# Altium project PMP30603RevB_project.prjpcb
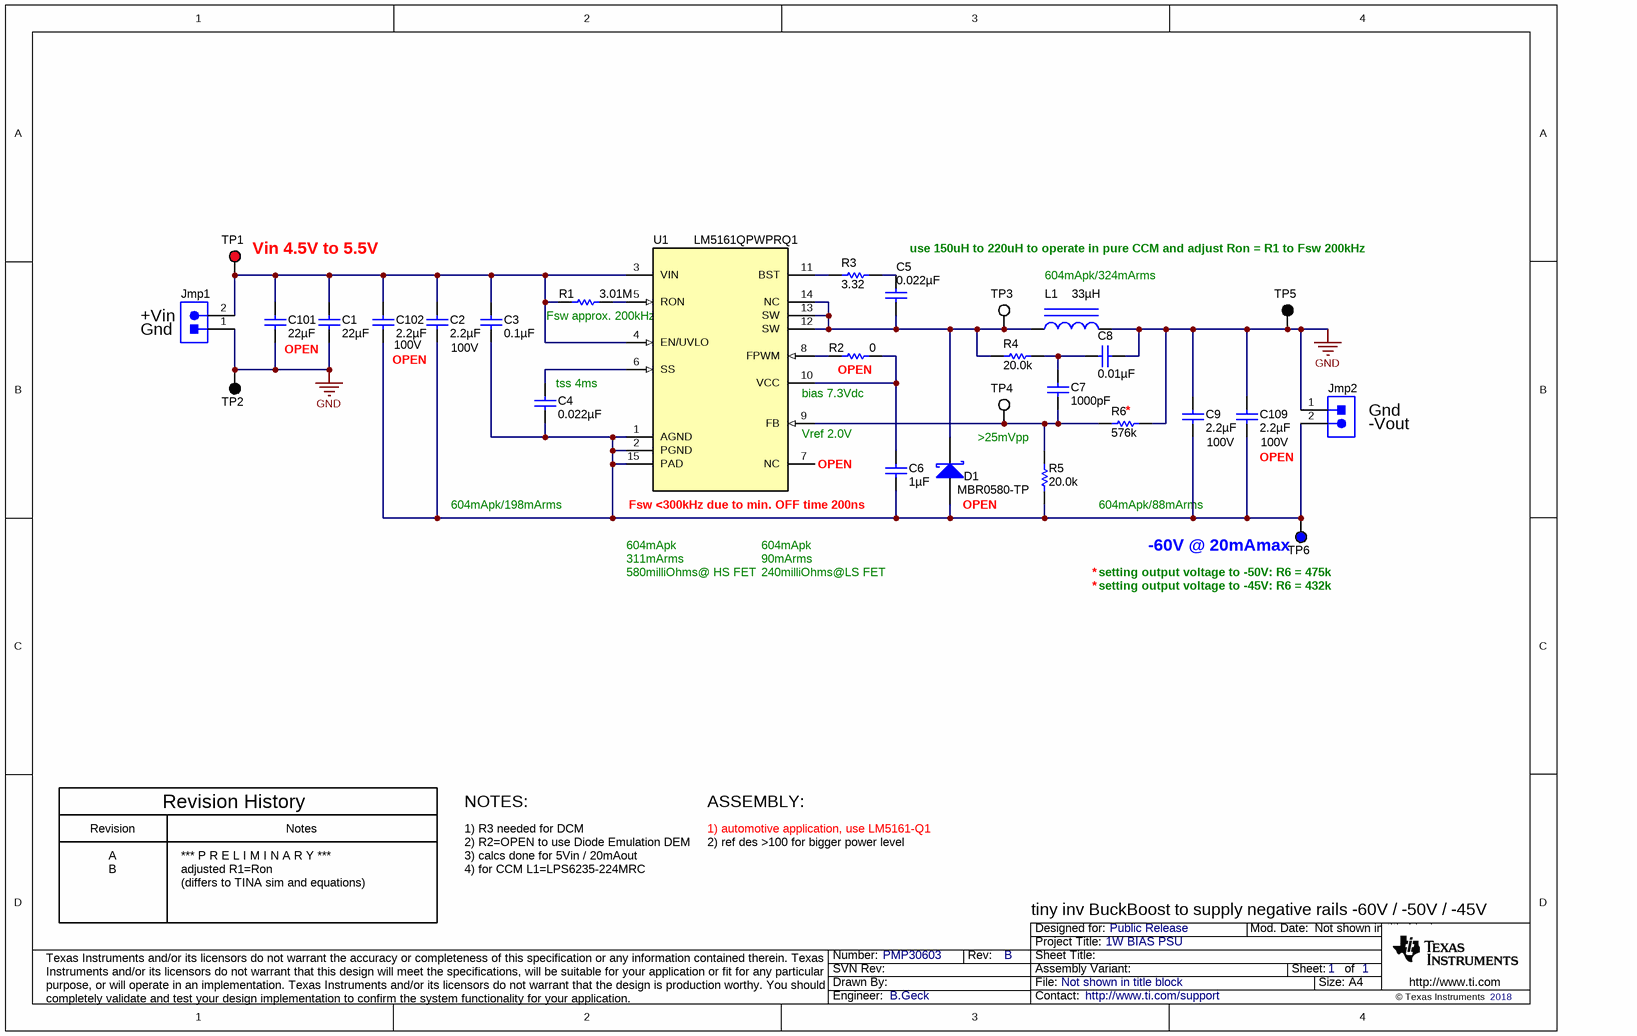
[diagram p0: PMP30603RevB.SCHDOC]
CopyrightYear: 2018; PCB_Layout: B.Geck; PCB_Rev: A; PRJ_Customer: Public Release; PRJ_Engineer: B.Geck; PRJ_Number: PMP30603; PRJ_Title: 1W BIAS PSU; SCH_Rev: B; TechSupport: http://www.ti.com/support
1 sheet, 29 parts. Net scope: global (net labels, ports and power ports of the same name join across sheets).
Board file: PMP30603RevA_board.PcbDoc

## Sheet PMP30603RevB.SCHDOC
size A4; Date: Not shown in title block; ApprovedBy: Not shown in title block; CheckedBy: Not shown in title block; Author: Not shown in title block; CompanyName: Not shown in title block; Engineer: Not shown in title block; Organization: Not shown in title block; Address1: Not shown in title block; Address2: Not shown in title block; Address3: Not shown in title block; Address4: Not shown in title block; DocumentNumber: 1; Revision: Use project parameter SCH_Rev; SheetNumber: 1; SheetTotal: 1; PageSetup: Record=PageOptions¦CenterHorizontal=True¦CenterVertical=True¦PrintScale=0.70¦XCorrection=1.00¦YCorrection=1.00¦PrintKind=0¦BorderSize=5000000¦LeftOffset=0¦BottomOffset=0¦Orientation=2¦PaperLength=1000¦PaperWidth=1000¦Scale=100¦PaperSource=15¦PrintQuality=600¦MediaType=1¦DitherType=10¦PaperKind=A4¦PrintScaleMode=1

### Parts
C1  ValueDisplayed: 22µF  [1206_180]  (hidden comment: GCM31CR71A226KE02)
C2  ValueDisplayed: 2.2µF  Value2: 100V  [1206_190]  (hidden comment: GRM31CR72A225KA73L)
C3  ValueDisplayed: 0.1µF  [0603]  (hidden comment: GRM188R72A104KA35D)
C4  ValueDisplayed: 0.022µF  [0603]  (hidden comment: GRM188R71C223KA01D)
C5  ValueDisplayed: 0.022µF  [0603]  (hidden comment: GRM188R71C223KA01D)
C6  ValueDisplayed: 1µF  [0603]  (hidden comment: GRM188R71E105KA12D)
C7  ValueDisplayed: 1000pF  [0603]  (hidden comment: GRM188R72A102KA01D)
C8  ValueDisplayed: 0.01µF  [0603]  (hidden comment: GRM188R72A103KA01D)
C9  ValueDisplayed: 2.2µF  Value2: 100V  [1206_190]  (hidden comment: GRM31CR72A225KA73L)
C101  ValueDisplayed: 22µF  [1206_180]  (hidden comment: GCM31CR71A226KE02)
C102  ValueDisplayed: 2.2µF  Value2: 100V  [1206_190]  (hidden comment: GRM31CR72A225KA73L)
C109  ValueDisplayed: 2.2µF  Value2: 100V  [1206_190]  (hidden comment: GRM31CR72A225KA73L)
D1  MBR0580-TP  [SOD-123]
Jmp1  TSW-102-07-G-S  [TSW-102-07-G-S]  (value not drawn)
Jmp2  TSW-102-07-G-S  [TSW-102-07-G-S]  (value not drawn)
L1  ValueDisplayed: 33µH  [LPS6235]  (hidden comment: LPS6235-333MLB)
R1  ValueDisplayed: 3.01M  [0603]  (hidden comment: CRCW06033M01FKEA)
R2  ValueDisplayed: 0  [0603]  (hidden comment: CRCW06030000Z0EA)
R3  ValueDisplayed: 3.32  [0603]  (hidden comment: CRCW06033R32FKEA)
R4  ValueDisplayed: 20.0k  [0603]  (hidden comment: CRCW060320K0FKEA)
R5  ValueDisplayed: 20.0k  [0603]  (hidden comment: CRCW060320K0FKEA)
R6  ValueDisplayed: 576k  [0603]  (hidden comment: CRCW0603576KFKEA)
TP1  5000  [Keystone5000]  (value not drawn)
TP2  5001  [Keystone5001]  (value not drawn)
TP3  5002  [Keystone5002]  (value not drawn)
TP4  5002  [Keystone5002]  (value not drawn)
TP5  5001  [Keystone5001]  (value not drawn)
TP6  5117  [Keystone5117]  (value not drawn)
U1  LM5161QPWPRQ1  [PWP0014A_N]

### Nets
GND: C1.2 C8.1 C9.1 C101.2 C109.1 Jmp1.1 Jmp2.1 L1.2 R6.2 TP2.1 TP5.1
NetC1_1: C1.1 C2.1 C3.1 C101.1 C102.1 Jmp1.2 R1.1 TP1.1 U1.3(VIN) U1.4(EN/UVLO)
NetC2_2: C2.2 C3.2 C4.2 C6.2 C9.2 C102.2 C109.2 D1.2(A) Jmp2.2 R5.1 TP6.1 U1.1(AGND) U1.2(PGND) U1.15(PAD)
NetC4_1: C4.1 U1.6(SS)
NetC5_1: C5.1 R3.2
NetC5_2: C5.2 D1.1(K) L1.1 R4.1 TP3.1 U1.12(SW) U1.13(SW) U1.14(NC)
NetC6_1: C6.1 R2.2 U1.10(VCC)
NetC7_1: C7.1 C8.2 R4.2
NetC7_2: C7.2 R5.2 R6.1 TP4.1 U1.9(FB)
NetR1_2: R1.2 U1.5(RON)
NetR2_1: R2.1 U1.8(FPWM)
NetR3_1: R3.1 U1.11(BST)

Not connected (* = marked no-connect by the designer): U1 7(NC)

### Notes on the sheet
- (near TP1) Vin 4.5V to 5.5V
- use 150uH to 220uH to operate in pure CCM and adjust Ron = R1 to Fsw 200kHz
- (near Jmp1) +Vin
- (near U1) Fsw approx. 200kHz
- 604mApk/324mArms
- (near Jmp1) Gnd
- OPEN
- (near C4) tss 4ms
- (near R2) OPEN
- (near U1) Vref 2.0V
- (near U1) bias 7.3Vdc
- >25mVpp
- (near R6) *
- (near Jmp2) Gnd
- (near Jmp2) -Vout
- 604mApk/198mArms
- Fsw <300kHz due to min. OFF time 200ns
- (near D1) OPEN
- 604mApk/88mArms
- 604mApk
- 580milliOhms@ HS FET
- 311mArms
- 240milliOhms@LS FET
- 90mArms
- *
- (near TP6) setting output voltage to -50V: R6 = 475k
- (near TP6) setting output voltage to -45V: R6 = 432k
- (near TP6) -60V @ 20mAmax
- Revision
- A
- *** P R E L I M I N A R Y ***
- Revision History
- Notes
- NOTES:
- 3) calcs done for 5Vin / 20mAout
- 1) R3 needed for DCM
- 2) R2=OPEN to use Diode Emulation DEM
- ASSEMBLY:
- 1) automotive application, use LM5161-Q1
- 2) ref des >100 for bigger power level
- B
- adjusted R1=Ron
- (differs to TINA sim and equations)
- 4) for CCM L1=LPS6235-224MRC
- tiny inv BuckBoost to supply negative rails -60V / -50V / -45V

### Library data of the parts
C1 C101 = GCM31CR71A226KE02: CAP, CERM, 22 µF, 10 V,+/- 10%, X7R, AEC-Q200 Grade 1, 1206; Manufacturer: MuRata; Polarized: N; CompType: Capacitor; Value: 22uF; U/M: EA; Cap_F: 0.000022; Tolerance_%: 10; Value2: 10V; TaMin_C: -55; TaMax_C: 125; Cap_Case: 1206; SizeArea_mm2: 5.12; SizeAreaWB_mm2: 10.92; SizeX_mm: 3.2; SizeY_mm: 1.6; SizeZ_mm: 1.8; AEC Category: Q200; AEC Qualified: Y; AEC Grade: 1
C2 C9 C102 C109 = GRM31CR72A225KA73L: CAP, CERM, 2.2 µF, 100 V,+/- 10%, X7R, 1206; Manufacturer: MuRata; Polarized: N; CompType: Capacitor; Value: 2.2uF; U/M: EA; Cap_F: 0.0000022; Tolerance_%: 10; VDC_V: 100; TaMin_C: -55; TaMax_C: 125; Cap_Case: 1206; SizeArea_mm2: 5.12; SizeAreaWB_mm2: 10.92; SizeX_mm: 3.2; SizeY_mm: 1.6; SizeZ_mm: 1.9; AEC Category: Q200; Green_Lifecycle: Active; Green_REACh: Passed
C3 = GRM188R72A104KA35D: CAP, CERM, 0.1 µF, 100 V,+/- 10%, X7R, 0603; Manufacturer: MuRata; Polarized: N; CompType: Capacitor; Value: 0.1uF; U/M: EA; Cap_F: 0.0000001; Tolerance_%: 10; Value1: Unknown; VDC_V: 100; Value2: 100V; TaMin_C: -55; TaMax_C: 125; SizeArea_mm2: 1.28; SizeAreaWB_mm2: 4.68; SizeX_mm: 1.6; SizeY_mm: 0.8; SizeZ_mm: 1; AEC Category: Q200; Green_Lifecycle: Active; Green_REACh: Passed
C4 C5 = GRM188R71C223KA01D: CAP, CERM, 0.022 µF, 16 V,+/- 10%, X7R, 0603; Manufacturer: MuRata; Polarized: N; CompType: Capacitor; Value: 0.022uF; U/M: EA; Cap_F: 0.000000022; Tolerance_%: 10; VDC_V: 16; Value2: 16V; TaMin_C: -55; TaMax_C: 125; SizeArea_mm2: 1.28; SizeAreaWB_mm2: 4.68; SizeX_mm: 1.6; SizeY_mm: 0.8; SizeZ_mm: 1; AEC Category: Q200; Green_Lifecycle: Active; Green_REACh: Passed
C6 = GRM188R71E105KA12D: CAP, CERM, 1 µF, 25 V,+/- 10%, X7R, 0603; Manufacturer: MuRata; Polarized: N; CompType: Capacitor; Value: 1uF; U/M: EA; Cap_F: 0.000001; Tolerance_%: 10; VDC_V: 25; Value2: 25V; TaMin_C: -55; TaMax_C: 125; SizeArea_mm2: 1.28; SizeAreaWB_mm2: 4.68; SizeX_mm: 1.6; SizeY_mm: 0.8; SizeZ_mm: 1; AEC Category: Q200; Green_Lifecycle: Active; Green_REACh: Passed
C7 = GRM188R72A102KA01D: CAP, CERM, 1000 pF, 100 V,+/- 10%, X7R, 0603; Manufacturer: MuRata; Polarized: N; CompType: Capacitor; Value: 1000pF; U/M: EA; Cap_F: 0.000000001; Tolerance_%: 10; VDC_V: 100; Value2: 100V; TaMin_C: -55; TaMax_C: 125; SizeArea_mm2: 1.28; SizeAreaWB_mm2: 4.68; SizeX_mm: 1.6; SizeY_mm: 0.8; SizeZ_mm: 1; AEC Category: Q200; Green_Lifecycle: Active; Green_REACh: Passed
C8 = GRM188R72A103KA01D: CAP, CERM, 0.01 µF, 100 V,+/- 10%, X7R, 0603; Manufacturer: MuRata; Polarized: N; CompType: Capacitor; Value: 0.01uF; U/M: EA; Cap_F: 0.00000001; Tolerance_%: 10; VDC_V: 100; Value2: 100V; TaMin_C: -55; TaMax_C: 125; SizeArea_mm2: 1.28; SizeAreaWB_mm2: 4.68; SizeX_mm: 1.6; SizeY_mm: 0.8; SizeZ_mm: 1; AEC Category: Q200; Green_Lifecycle: Active; Green_REACh: Passed
D1 = MBR0580-TP: Diode, Schottky, 80 V, 0.5 A, SOD-123; Manufacturer: Micro Commercial Components; U/M: EA; Vf_V: 0.8; Value: 80V; Value1: 0.5A; Value2: 0.8V; Io_A: 0.5; Vr_V: 80; TJmax_C: 150; SizeAreaWB_mm2: 13.095; SizeArea_mm2: 6.545; SizeX_mm: 3.85; SizeY_mm: 1.7; SizeZ_mm: 1.35; AEC Category: Q101; Green_Lifecycle: Not Set; Green_REACh: Incomplete
Jmp1 Jmp2 = TSW-102-07-G-S: Header, 100mil, 2x1, Gold, TH; Manufacturer: Samtec; SymbolCreator: a0412235; U/M: EA
L1 = LPS6235-333MLB: Inductor, Shielded Drum Core, Ferrite, 33 µH, 1.3 A, 0.18 ohm, SMD; Manufacturer: Coilcraft; Value: 33uH; Ind_H: 33.0E-6; Imax_A: 1.3; Irms: 1.3A @ 40C rise; Isat: 1.5A @ 30% inductance drop; DCR_ohm: 0.18; Value2: 1.3A; SizeAreaWB_mm2: 64; SizeArea_mm2: 36; SizeX_mm: 6; SizeZ_mm: 3.5; AEC Category: Q200; Green_Lifecycle: Not Set; Green_REACh: Incomplete
R1 = CRCW06033M01FKEA: RES, 3.01 M, 1%, 0.1 W, 0603; Manufacturer: Vishay-Dale; CompType: Resistor; Value: 3.01Meg; Res_ohm: 3010000; Value_Code: 3M01; Tolerance_%: 1; Power_W: 0.1; Value2: 0.1W; VDC_V: 75; TempCo: 100 ppm/C; SizeArea_mm2: 1.28; SizeX_mm: 1.6; SizeY_mm: 0.8; EIA_Code: E96; U/M: EA; AEC Category: Q200; Green_Lifecycle: Active; Green_REACh: Passed
R2 = CRCW06030000Z0EA: RES, 0, 5%, 0.1 W, 0603; Manufacturer: Vishay-Dale; CompType: Resistor; Value: 0; Value_Code: 0000; Tolerance_%: 5; Power_W: 0.1; Value2: 0.1W; VDC_V: 75; TempCo: 200 ppm/C; SizeArea_mm2: 1.28; SizeX_mm: 1.6; SizeY_mm: 0.8; SizeZ_mm: 1; EIA_Code: E24; U/M: EA; AEC Category: Q200; Green_Lifecycle: Active; Green_REACh: Passed
R3 = CRCW06033R32FKEA: RES, 3.32, 1%, 0.1 W, 0603; Manufacturer: Vishay-Dale; CompType: Resistor; Value: 3.32; Value_Code: 3R32; Tolerance_%: 1; Power_W: 0.1; Value2: 0.1W; VDC_V: 75; TempCo: 100 ppm/C; SizeArea_mm2: 1.28; SizeX_mm: 1.6; SizeY_mm: 0.8; EIA_Code: E96; U/M: EA; AEC Category: Q200
R4 R5 = CRCW060320K0FKEA: RES, 20.0 k, 1%, 0.1 W, 0603; Manufacturer: Vishay-Dale; CompType: Resistor; Value: 20.0k; Res_ohm: 20000; Value_Code: 20k0; Tolerance_%: 1; Power_W: 0.1; Value2: 0.1W; VDC_V: 75; TempCo: 100 ppm/C; SizeArea_mm2: 1.28; SizeX_mm: 1.6; SizeY_mm: 0.8; EIA_Code: E96; U/M: EA; AEC Category: Q200; Green_Lifecycle: Active; Green_REACh: Passed
R6 = CRCW0603576KFKEA: RES, 576 k, 1%, 0.1 W, 0603; Manufacturer: Vishay-Dale; CompType: Resistor; Value: 576k; Res_ohm: 576000; Tolerance_%: 1; Power_W: 0.1; Value2: 0.1W; VDC_V: 75; TempCo: 100 ppm/C; SizeArea_mm2: 1.28; SizeX_mm: 1.6; SizeY_mm: 0.8; EIA_Code: E96; U/M: EA; AEC Category: Q200
TP1 = 5000: Test Point, Miniature, Red, TH; Manufacturer: Keystone; CompType: Test Point Loop; U/M: EA
TP2 TP5 = 5001: Test Point, Miniature, Black, TH; Manufacturer: Keystone; CompType: Test Point Loop; U/M: EA
TP3 TP4 = 5002: Test Point, Miniature, White, TH; Manufacturer: Keystone; CompType: Test Point Loop; U/M: EA
TP6 = 5117: Test Point, Miniature, Blue, TH; Manufacturer: Keystone; CompType: Test Point Loop; U/M: EA; ContactFinish: Silver; Green_Lifecycle: Active; Green_REACh: Passed
U1 = LM5161QPWPRQ1: Wide Input 4.5-V to 100-V, 1-A Synchronous Buck / Fly-Buck Converter, PWP0014A (TSSOP-14); Alternate PartNumber: LM5161QPWPTQ1; Manufacturer: Texas Instruments; SymbolCreator: a0411947; SizeArea_mm2: 32; SizeAreaWB_mm2: 58.8; SizeX_mm: 6.4; SizeY_mm: 5; SizeZ_mm: 1.2; CompType: IC; U/M: EA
